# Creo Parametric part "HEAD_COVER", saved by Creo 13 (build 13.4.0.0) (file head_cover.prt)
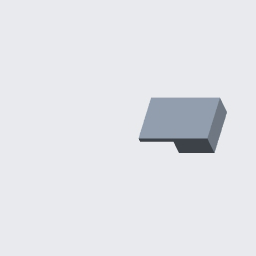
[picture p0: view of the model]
Units: millimeter Newton Second (mmNs); MM, TONNE, SECS

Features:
  1. datum plane "RIGHT"
  2. datum plane "TOP"
  3. datum plane "FRONT"
  4. coordinate system
  5. datum plane "DTM4"
  6. datum plane "DTM5"
  7. protrusion
  8. datum plane "DTM1"
  9. datum plane "DTM2"
  10. protrusion
  11. datum plane "DTM6"
  12. datum plane "DTM7"
  13. protrusion
  14. protrusion
  15. datum plane "DTM3"
  16. protrusion
  17. protrusion

Surfaces: 14 plane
